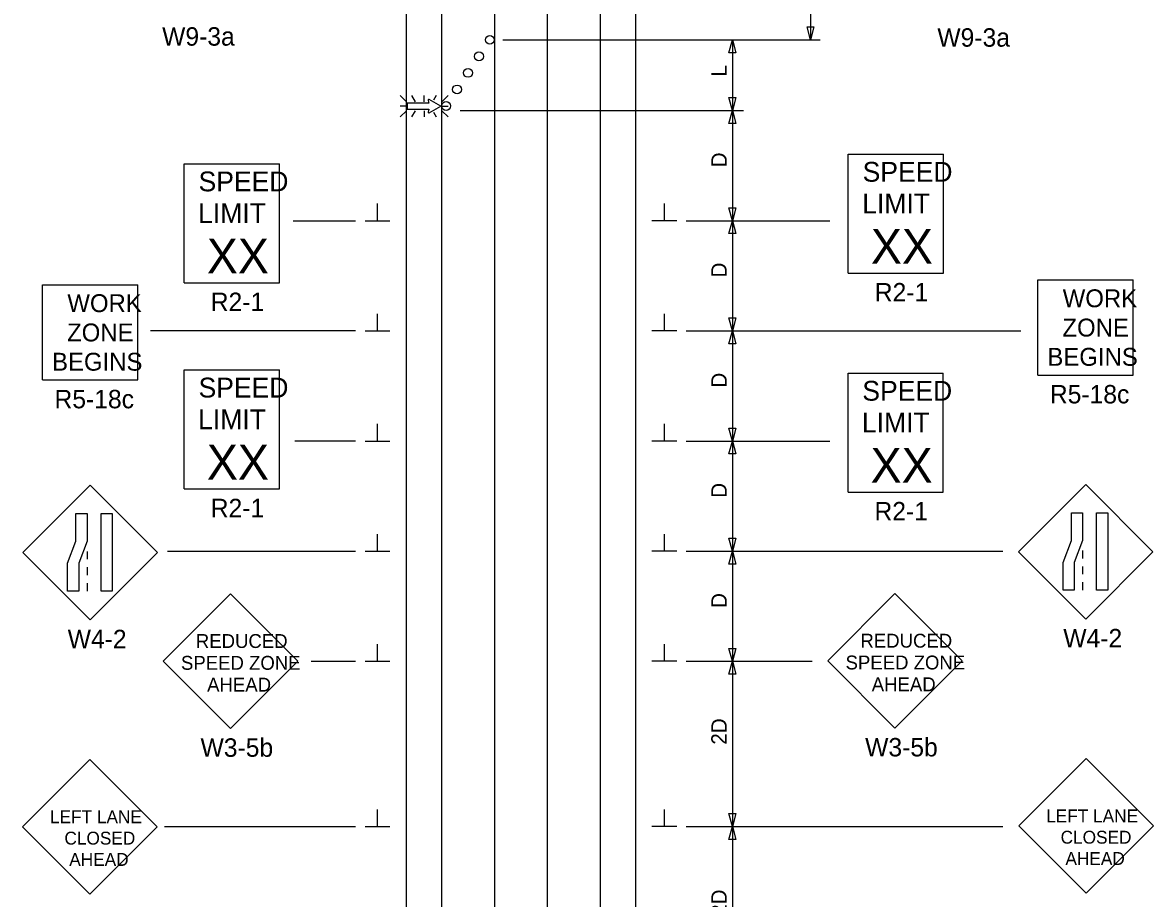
# Model space of a CAD drawing. Extents: x 16726 to 18482, y 5650 to 7013.
# Drawn here: x 16729 to 17242, y 6169 to 6566 of the extents above; entities that cross this region are included whole.
import ezdxf

# ---------------------------------------------------------------- set-up
doc = ezdxf.new("R2010")
doc.units = 0
for name, color, linetype in [('ALI_LEGAL_EX', 7, 'Continuous'), ('PAVT_EDGE_EX', 7, 'Continuous'), ('TRAFFIC_SIGNS_PR', 7, 'Continuous'), ('TYPICAL_TEXT_DIMEN_PR', 7, 'Continuous')]:
    doc.layers.add(name, color=color, linetype=linetype)

msp = doc.modelspace()

# ---------------------------------------------------------------- linework, layer by layer
at = {"layer": 'ALI_LEGAL_EX'}
for p, q in [((16943.36, 7013.47), (16943.36, 6195.33)), ((16967.36, 7013.47), (16967.36, 6195.33)), ((16943.36, 6961.56), (16943.36, 6097.65)), ((16967.36, 6961.56), (16967.36, 6097.65))]:
    msp.add_line(p, q, dxfattribs=at)
for points in [[(16943.36, 6524.34), (16943.36, 6499.34)], [(16943.36, 6524.34), (16943.36, 6499.34)], [(16943.36, 6524.34), (16943.36, 6499.34)], [(16943.36, 6524.34), (16943.36, 6499.34)], [(16943.36, 6524.34), (16943.36, 6499.34)], [(16967.36, 6524.34), (16967.36, 6499.34)], [(16967.36, 6524.34), (16967.36, 6499.34)], [(16967.36, 6524.34), (16967.36, 6499.34)], [(16967.36, 6524.34), (16967.36, 6499.34)], [(16967.36, 6524.34), (16967.36, 6499.34)], [(16943.36, 6424.34), (16943.36, 6399.34)], [(16943.36, 6424.34), (16943.36, 6399.34)], [(16943.36, 6424.34), (16943.36, 6399.34)], [(16943.36, 6424.34), (16943.36, 6399.34)], [(16943.36, 6424.34), (16943.36, 6399.34)], [(16967.36, 6424.34), (16967.36, 6399.34)], [(16967.36, 6424.34), (16967.36, 6399.34)], [(16967.36, 6424.34), (16967.36, 6399.34)], [(16967.36, 6424.34), (16967.36, 6399.34)], [(16967.36, 6424.34), (16967.36, 6399.34)], [(16943.36, 6324.34), (16943.36, 6299.34)], [(16943.36, 6324.34), (16943.36, 6299.34)], [(16943.36, 6324.34), (16943.36, 6299.34)], [(16943.36, 6324.34), (16943.36, 6299.34)], [(16943.36, 6324.34), (16943.36, 6299.34)], [(16967.36, 6324.34), (16967.36, 6299.34)], [(16967.36, 6324.34), (16967.36, 6299.34)], [(16967.36, 6324.34), (16967.36, 6299.34)], [(16967.36, 6324.34), (16967.36, 6299.34)], [(16967.36, 6324.34), (16967.36, 6299.34)], [(16943.36, 6224.34), (16943.36, 6199.34)], [(16943.36, 6224.34), (16943.36, 6199.34)], [(16943.36, 6224.34), (16943.36, 6199.34)], [(16943.36, 6224.34), (16943.36, 6199.34)], [(16967.36, 6224.34), (16967.36, 6199.34)], [(16967.36, 6224.34), (16967.36, 6199.34)], [(16967.36, 6224.34), (16967.36, 6199.34)], [(16967.36, 6224.34), (16967.36, 6199.34)], [(16967.36, 6224.34), (16967.36, 6199.34)]]:
    msp.add_lwpolyline(points, dxfattribs=at)
at = {"layer": 'PAVT_EDGE_EX'}
for p, q in [((16903.36, 6926.44), (16903.36, 6057.56)), ((16919.36, 6926.44), (16919.36, 6057.56)), ((16991.36, 6926.44), (16991.36, 6057.56)), ((17007.36, 6926.44), (17007.36, 6057.56))]:
    msp.add_line(p, q, dxfattribs=at)
at = {"layer": 'TRAFFIC_SIGNS_PR'}
for p, q in [((16903.38, 6530.22), (16900.56, 6533.04)), ((16905.67, 6533.04), (16907.3, 6530.22)), ((16911.46, 6530.22), (16911.46, 6533.04)), ((16916.93, 6533.04), (16915.72, 6530.95)), ((16922.37, 6533.04), (16919.55, 6530.22)), ((16903.38, 6528.19), (16900.56, 6528.19)), ((16903.38, 6526.16), (16900.56, 6523.34)), ((16907.33, 6526.16), (16905.7, 6523.34)), ((16911.46, 6526.16), (16911.46, 6523.34)), ((16915.65, 6525.52), (16916.91, 6523.34)), ((16919.55, 6528.19), (16922.37, 6528.19)), ((16922.37, 6523.34), (16919.55, 6526.16)), ((17104, 6506.48), (17147.2, 6506.48)), ((17104, 6452.48), (17104, 6506.48)), ((17147.2, 6452.48), (17147.2, 6506.48)), ((16802.57, 6502.12), (16845.77, 6502.12)), ((16802.57, 6448.12), (16802.57, 6502.12)), ((16845.77, 6448.12), (16845.77, 6502.12)), ((17104, 6452.48), (17147.2, 6452.48)), ((16738.25, 6403.98), (16738.25, 6447.18)), ((16738.25, 6447.18), (16781.45, 6447.18)), ((16781.45, 6403.98), (16781.45, 6447.18)), ((16802.57, 6448.12), (16845.77, 6448.12)), ((17190.07, 6406.19), (17190.07, 6449.39)), ((17190.07, 6449.39), (17233.27, 6449.39)), ((17233.27, 6406.19), (17233.27, 6449.39)), ((16802.57, 6408.54), (16845.77, 6408.54)), ((16802.57, 6354.54), (16802.57, 6408.54)), ((16845.77, 6354.54), (16845.77, 6408.54)), ((17103.86, 6407.09), (17147.06, 6407.09)), ((17103.86, 6353.09), (17103.86, 6407.09)), ((17147.06, 6353.09), (17147.06, 6407.09)), ((17190.07, 6406.19), (17233.27, 6406.19)), ((16738.25, 6403.98), (16781.45, 6403.98)), ((16759.83, 6356.18), (16729.28, 6325.63)), ((16790.37, 6325.63), (16759.83, 6356.18)), ((17211.75, 6356.56), (17181.2, 6326.01)), ((17242.3, 6326.01), (17211.75, 6356.56)), ((16802.57, 6354.54), (16845.77, 6354.54)), ((17103.86, 6353.09), (17147.06, 6353.09)), ((16729.28, 6325.63), (16759.83, 6295.08)), ((16758.42, 6326.18), (16758.42, 6322.58)), ((16759.83, 6295.08), (16790.37, 6325.63)), ((17181.2, 6326.01), (17211.75, 6295.47)), ((17210.35, 6326.57), (17210.35, 6322.97)), ((17211.75, 6295.47), (17242.3, 6326.01)), ((16758.42, 6318.98), (16758.42, 6315.38)), ((17210.35, 6319.37), (17210.35, 6315.77)), ((16758.42, 6311.78), (16758.42, 6308.18)), ((17210.35, 6312.17), (17210.35, 6308.57)), ((16823.51, 6306.89), (16792.96, 6276.34)), ((16854.05, 6276.34), (16823.51, 6306.89)), ((17125.18, 6307.05), (17094.63, 6276.5)), ((17155.73, 6276.5), (17125.18, 6307.05)), ((16792.96, 6276.34), (16823.51, 6245.8)), ((16823.51, 6245.8), (16854.05, 6276.34)), ((17094.63, 6276.5), (17125.18, 6245.96)), ((17125.18, 6245.96), (17155.73, 6276.5)), ((16759.73, 6231.73), (16729.18, 6201.19)), ((16790.28, 6201.19), (16759.73, 6231.73)), ((17211.93, 6232.15), (17181.38, 6201.6)), ((17242.47, 6201.6), (17211.93, 6232.15)), ((16729.18, 6201.19), (16759.73, 6170.64)), ((16759.73, 6170.64), (16790.28, 6201.19)), ((17181.38, 6201.6), (17211.93, 6171.06)), ((17211.93, 6171.06), (17242.47, 6201.6))]:
    msp.add_line(p, q, dxfattribs=at)
for points in [[(16913.29, 6530.87), (16913.52, 6529.58), (16903.8, 6529.58), (16903.8, 6526.83), (16913.52, 6526.83), (16913.29, 6525.53)], [(16913.79, 6525.18), (16919.1, 6528.19), (16913.79, 6531.23)]]:
    msp.add_lwpolyline(points, dxfattribs=at)
for points in [[(16758.42, 6343.33), (16758.42, 6330.76), (16754.66, 6320.76), (16754.66, 6308.18), (16749.6, 6308.18), (16749.6, 6320.76), (16753.37, 6330.76), (16753.37, 6343.33)], [(16769.83, 6343.33), (16769.83, 6308.18), (16764.77, 6308.18), (16764.77, 6343.33)], [(17210.35, 6343.72), (17210.35, 6331.14), (17206.58, 6321.14), (17206.58, 6308.57), (17201.53, 6308.57), (17201.53, 6321.14), (17205.29, 6331.14), (17205.29, 6343.72)], [(17221.75, 6343.72), (17221.75, 6308.57), (17216.7, 6308.57), (17216.7, 6343.72)]]:
    msp.add_lwpolyline(points, close=True, dxfattribs=at)
for centre in [(16941.29, 6558.37), (16936.33, 6550.85), (16931.36, 6543.35), (16926.39, 6535.85), (16921.42, 6528.34)]:
    msp.add_circle(centre, 2, dxfattribs=at)
for centre, start, end in [((16913.62, 6530.93), 61.4833, 189.9593), ((16913.62, 6525.47), 170.7308, 298.8916)]:
    msp.add_arc(centre, 0.341, start, end, dxfattribs=at)
at = {"layer": 'TYPICAL_TEXT_DIMEN_PR'}
for p, q in [((17086.84, 6676.24), (17086.84, 6558.37)), ((17086.84, 6558.37), (17085.27, 6564.23)), ((17085.27, 6564.23), (17086.84, 6564.23)), ((17086.84, 6564.23), (17088.41, 6564.23)), ((17088.41, 6564.23), (17086.84, 6558.37)), ((16947.11, 6558.37), (17091.17, 6558.37)), ((17049.79, 6552.51), (17051.36, 6558.37)), ((17051.36, 6558.37), (17051.36, 6526.26)), ((17051.36, 6558.37), (17052.93, 6552.51)), ((17051.36, 6552.51), (17049.79, 6552.51)), ((17052.93, 6552.51), (17051.36, 6552.51)), ((17051.36, 6526.26), (17049.79, 6532.12)), ((17049.79, 6532.12), (17051.36, 6532.12)), ((17051.36, 6532.12), (17052.93, 6532.12)), ((17052.93, 6532.12), (17051.36, 6526.26)), ((16927.76, 6526.26), (17056.36, 6526.26)), ((17049.79, 6520.4), (17051.36, 6526.26)), ((17051.36, 6526.26), (17051.36, 6476.26)), ((17051.36, 6526.26), (17052.93, 6520.4)), ((17051.36, 6520.4), (17049.79, 6520.4)), ((17052.93, 6520.4), (17051.36, 6520.4)), ((16890.23, 6476.26), (16890.23, 6484.05)), ((17020.48, 6476.26), (17020.48, 6484.05)), ((17051.36, 6476.26), (17049.79, 6482.12)), ((17049.79, 6482.12), (17051.36, 6482.12)), ((17051.36, 6482.12), (17052.93, 6482.12)), ((17052.93, 6482.12), (17051.36, 6476.26)), ((16851.96, 6476.26), (16880.36, 6476.26)), ((16884.61, 6476.26), (16895.86, 6476.26)), ((17026.11, 6476.26), (17014.86, 6476.26)), ((17030.36, 6476.26), (17095.61, 6476.26)), ((17049.79, 6470.4), (17051.36, 6476.26)), ((17051.36, 6476.26), (17051.36, 6426.26)), ((17051.36, 6476.26), (17052.93, 6470.4)), ((17051.36, 6470.4), (17049.79, 6470.4)), ((17052.93, 6470.4), (17051.36, 6470.4)), ((16890.23, 6426.26), (16890.23, 6434.05)), ((17020.48, 6426.26), (17020.48, 6434.05)), ((17051.36, 6426.26), (17049.79, 6432.12)), ((17049.79, 6432.12), (17051.36, 6432.12)), ((17051.36, 6432.12), (17052.93, 6432.12)), ((17052.93, 6432.12), (17051.36, 6426.26)), ((16880.36, 6426.26), (16787.26, 6426.26)), ((16884.61, 6426.26), (16895.86, 6426.26)), ((17026.11, 6426.26), (17014.86, 6426.26)), ((17030.36, 6426.26), (17182.34, 6426.26)), ((17030.36, 6426.26), (17095.61, 6426.26)), ((17049.79, 6420.4), (17051.36, 6426.26)), ((17051.36, 6426.26), (17052.93, 6420.4)), ((17051.36, 6426.26), (17051.36, 6376.26)), ((17051.36, 6420.4), (17049.79, 6420.4)), ((17052.93, 6420.4), (17051.36, 6420.4)), ((16890.23, 6376.26), (16890.23, 6384.05)), ((17020.48, 6376.26), (17020.48, 6384.05)), ((17051.36, 6376.26), (17049.79, 6382.12)), ((17049.79, 6382.12), (17051.36, 6382.12)), ((17051.36, 6382.12), (17052.93, 6382.12)), ((17052.93, 6382.12), (17051.36, 6376.26)), ((16880.36, 6376.26), (16852.74, 6376.26)), ((16884.61, 6376.26), (16895.86, 6376.26)), ((17026.11, 6376.26), (17014.86, 6376.26)), ((17030.36, 6376.26), (17095.61, 6376.26)), ((17049.79, 6370.4), (17051.36, 6376.26)), ((17051.36, 6376.26), (17051.36, 6326.26)), ((17051.36, 6376.26), (17052.93, 6370.4)), ((17051.36, 6370.4), (17049.79, 6370.4)), ((17052.93, 6370.4), (17051.36, 6370.4)), ((16890.23, 6326.26), (16890.23, 6334.05)), ((17020.48, 6326.26), (17020.48, 6334.05)), ((17051.36, 6326.26), (17049.79, 6332.12)), ((17049.79, 6332.12), (17051.36, 6332.12)), ((17051.36, 6332.12), (17052.93, 6332.12)), ((17052.93, 6332.12), (17051.36, 6326.26)), ((16795.02, 6326.26), (16880.36, 6326.26)), ((16884.61, 6326.26), (16895.86, 6326.26)), ((17026.11, 6326.26), (17014.86, 6326.26)), ((17030.36, 6326.26), (17174.21, 6326.26)), ((17049.79, 6320.4), (17051.36, 6326.26)), ((17051.36, 6326.26), (17051.36, 6276.26)), ((17051.36, 6326.26), (17052.93, 6320.4)), ((17051.36, 6320.4), (17049.79, 6320.4)), ((17052.93, 6320.4), (17051.36, 6320.4)), ((16890.23, 6276.26), (16890.23, 6284.05)), ((17020.48, 6276.26), (17020.48, 6284.05)), ((17051.36, 6276.26), (17049.79, 6282.12)), ((17049.79, 6282.12), (17051.36, 6282.12)), ((17051.36, 6282.12), (17052.93, 6282.12)), ((17052.93, 6282.12), (17051.36, 6276.26)), ((16860.16, 6276.26), (16880.36, 6276.26)), ((16884.61, 6276.26), (16895.86, 6276.26)), ((17026.11, 6276.26), (17014.86, 6276.26)), ((17030.36, 6276.26), (17087.57, 6276.26)), ((17049.79, 6270.4), (17051.36, 6276.26)), ((17051.36, 6276.26), (17051.36, 6201.26)), ((17051.36, 6276.26), (17052.93, 6270.4)), ((17051.36, 6270.4), (17049.79, 6270.4)), ((17052.93, 6270.4), (17051.36, 6270.4)), ((16890.23, 6201.26), (16890.23, 6209.05)), ((17020.48, 6201.26), (17020.48, 6209.05)), ((17051.36, 6201.26), (17049.79, 6207.12)), ((17049.79, 6207.12), (17051.36, 6207.12)), ((17051.36, 6207.12), (17052.93, 6207.12)), ((17052.93, 6207.12), (17051.36, 6201.26)), ((16793.61, 6201.26), (16880.36, 6201.26)), ((16884.61, 6201.26), (16895.86, 6201.26)), ((17026.11, 6201.26), (17014.86, 6201.26)), ((17030.36, 6201.26), (17174.21, 6201.26)), ((17049.79, 6195.4), (17051.36, 6201.26)), ((17051.36, 6201.26), (17051.36, 6126.26)), ((17051.36, 6201.26), (17052.93, 6195.4)), ((17051.36, 6195.4), (17049.79, 6195.4)), ((17052.93, 6195.4), (17051.36, 6195.4))]:
    msp.add_line(p, q, dxfattribs=at)

# ---------------------------------------------------------------- texts
at = {"layer": 'TRAFFIC_SIGNS_PR'}
for s, height, p in [('W9-3a', 8.37, (16792.51, 6555.71)), ('W9-3a', 8.37, (17144.41, 6555.24)), ('SPEED', 9, (16809.05, 6489.59)), ('SPEED', 9, (17110.49, 6493.95)), ('LIMIT', 9, (17110.3, 6479.55)), ('LIMIT', 9, (16808.87, 6475.19)), ('XX', 15.785, (16812.82, 6452.35)), ('XX', 15.785, (17114.25, 6456.71)), ('R2-1', 8.37, (17116.01, 6439.61)), ('WORK', 8.119, (16749.5, 6434.77)), ('R2-1', 8.37, (16814.58, 6435.25)), ('WORK', 8.119, (17201.32, 6436.98)), ('ZONE', 8.119, (17201.19, 6423.69)), ('ZONE', 8.119, (16749.37, 6421.48)), ('BEGINS', 8.119, (16742.54, 6408.19)), ('BEGINS', 8.119, (17194.36, 6410.41)), ('SPEED', 9, (16809.05, 6396.01)), ('SPEED', 9, (17110.35, 6394.56)), ('R5-18c', 8.37, (17195.49, 6393.32)), ('R5-18c', 8.37, (16743.66, 6391.11)), ('LIMIT', 9, (16808.87, 6381.61)), ('LIMIT', 9, (17110.17, 6380.16)), ('XX', 15.785, (16812.82, 6358.77)), ('XX', 15.785, (17114.11, 6357.32)), ('R2-1', 8.37, (16814.58, 6341.67)), ('R2-1', 8.37, (17115.87, 6340.23)), ('W4-2', 8.37, (16749.65, 6282.22)), ('REDUCED', 6.3, (16807.82, 6282.32)), ('REDUCED', 6.3, (17109.49, 6282.47)), ('W4-2', 8.37, (17201.58, 6282.6)), ('SPEED ZONE', 6.3, (16801.06, 6272.42)), ('SPEED ZONE', 6.3, (17102.74, 6272.57)), ('AHEAD', 6.3, (16812.94, 6262.52)), ('AHEAD', 6.3, (17114.62, 6262.67)), ('W3-5b', 8.37, (16809.95, 6232.93)), ('W3-5b', 8.37, (17111.63, 6233.09)), ('LEFT LANE', 5.85, (16741.6, 6202.76)), ('LEFT LANE', 5.85, (17193.8, 6203.18)), ('CLOSED', 5.85, (16748.16, 6193.08)), ('CLOSED', 5.85, (17200.36, 6193.5)), ('AHEAD', 5.85, (16750.35, 6183.41)), ('AHEAD', 5.85, (17202.55, 6183.83))]:
    msp.add_text(s, height=height, dxfattribs=at).set_placement(p)
at = {"layer": 'TYPICAL_TEXT_DIMEN_PR'}
for s, p in [('L', (17048.8, 6541.67)), ('D', (17048.8, 6500.48)), ('D', (17048.8, 6450.48)), ('D', (17048.8, 6400.48)), ('D', (17048.8, 6350.48)), ('D', (17048.8, 6300.48)), ('2D', (17048.8, 6238.42)), ('2D', (17048.8, 6160.73))]:
    msp.add_text(s, height=7, rotation=90, dxfattribs=at).set_placement(p)

doc.saveas('drawing.dxf')
